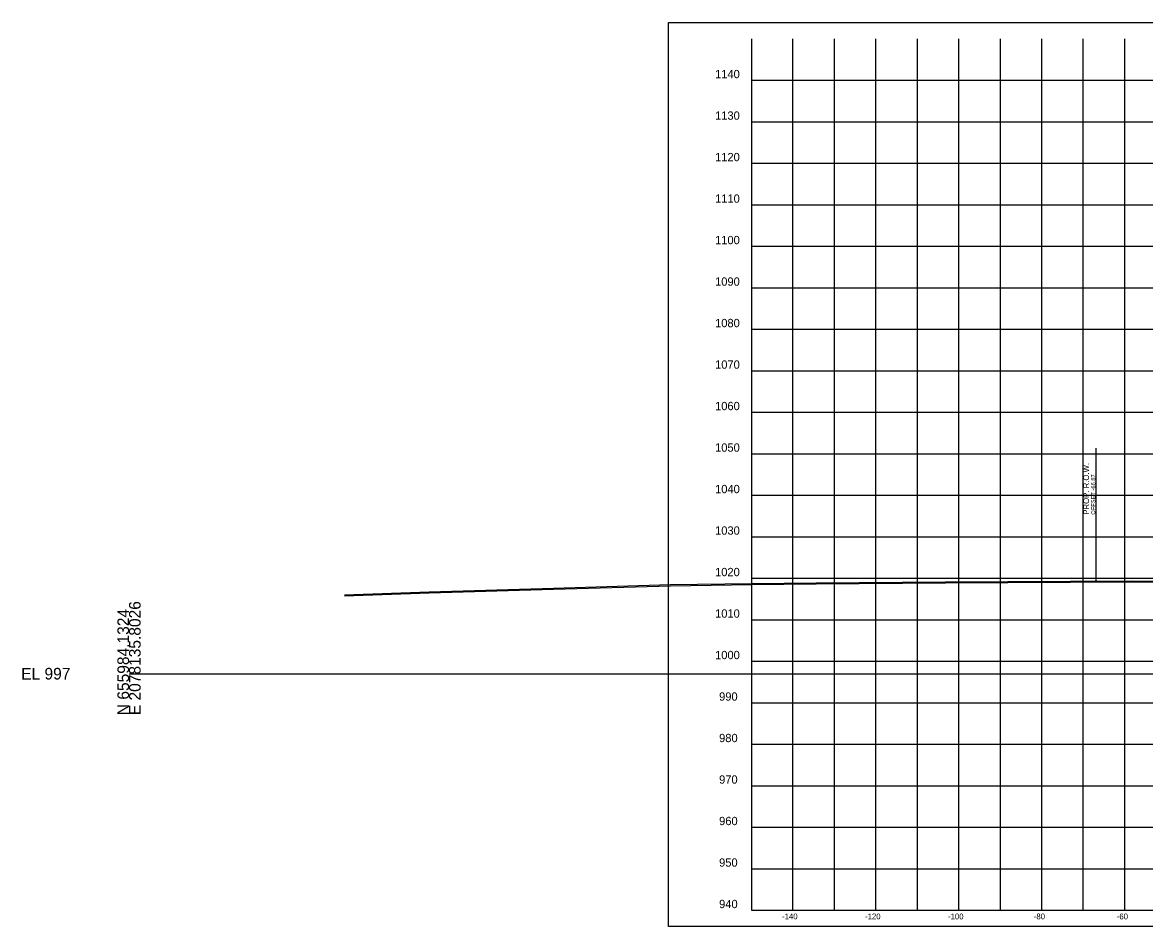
# Model space of a CAD drawing. Extents: x 5868 to 6683, y 2883 to 19120.
# Drawn here: x 5868.1 to 6138.5, y 10384.1 to 10602 of the extents above; entities that cross this region are included whole.
import ezdxf

# ---------------------------------------------------------------- set-up
doc = ezdxf.new("R2010")
doc.units = 0
for name, color, linetype in [('DESIGN - ROW - Right-of-Way and Easement Labels', 7, 'Continuous'), ('DESIGN - ROW - Right-of-Way Linework', 7, 'Continuous'), ('DESIGN - SHEET - Corner Text', 7, 'Continuous'), ('DESIGN - SHEET - Light Grid', 7, 'Continuous'), ('DESIGN - SHEET - Linework', 7, 'Continuous'), ('DESIGN - SHEET - Plot Shape', 7, 'Continuous'), ('SURVEY - GROUND - Bottom of Topsoil Layer', 7, 'Continuous'), ('SURVEY - GROUND - Top of Ground', 7, 'Continuous')]:
    doc.layers.add(name, color=color, linetype=linetype)

msp = doc.modelspace()

# ---------------------------------------------------------------- linework, layer by layer
at = {"layer": 'DESIGN - ROW - Right-of-Way Linework'}
msp.add_line((6126.91, 10467.38), (6126.91, 10499.38), dxfattribs=at)
at = {"layer": 'DESIGN - SHEET - Light Grid'}
msp.add_line((5893.78, 10445.07), (6193.78, 10445.07), dxfattribs=at)
at = {"layer": 'DESIGN - SHEET - Linework'}
for p, q in [((6053.78, 10388.07), (6053.78, 10598.07)), ((6063.78, 10388.07), (6063.78, 10598.07)), ((6073.78, 10388.07), (6073.78, 10598.07)), ((6083.78, 10388.07), (6083.78, 10598.07)), ((6093.78, 10388.07), (6093.78, 10598.07)), ((6103.78, 10388.07), (6103.78, 10598.07)), ((6113.78, 10388.07), (6113.78, 10598.07)), ((6123.78, 10388.07), (6123.78, 10598.07)), ((6133.78, 10388.07), (6133.78, 10598.07)), ((6043.78, 10588.07), (6343.78, 10588.07)), ((6043.78, 10578.07), (6343.78, 10578.07)), ((6043.78, 10568.07), (6343.78, 10568.07)), ((6043.78, 10558.07), (6343.78, 10558.07)), ((6043.78, 10548.07), (6343.78, 10548.07)), ((6043.78, 10538.07), (6343.78, 10538.07)), ((6043.78, 10528.07), (6343.78, 10528.07)), ((6043.78, 10518.07), (6343.78, 10518.07)), ((6043.78, 10508.07), (6343.78, 10508.07)), ((6043.78, 10498.07), (6343.78, 10498.07)), ((6043.78, 10488.07), (6343.78, 10488.07)), ((6043.78, 10478.07), (6343.78, 10478.07)), ((6043.78, 10468.07), (6343.78, 10468.07)), ((6043.78, 10458.07), (6343.78, 10458.07)), ((6043.78, 10448.07), (6343.78, 10448.07)), ((6043.78, 10438.07), (6343.78, 10438.07)), ((6043.78, 10428.07), (6343.78, 10428.07)), ((6043.78, 10418.07), (6343.78, 10418.07)), ((6043.78, 10408.07), (6343.78, 10408.07)), ((6043.78, 10398.07), (6343.78, 10398.07))]:
    msp.add_line(p, q, dxfattribs=at)
msp.add_lwpolyline([(6043.78, 10598.07), (6043.78, 10388.07), (6343.78, 10388.07), (6343.78, 10598.07)], dxfattribs=at)
at = {"layer": 'DESIGN - SHEET - Plot Shape'}
msp.add_lwpolyline([(6023.78, 10602.01), (6363.78, 10602.01), (6363.78, 10384.13), (6023.78, 10384.13)], close=True, dxfattribs=at)
at = {"layer": 'SURVEY - GROUND - Bottom of Topsoil Layer'}
for p, q in [((5996.12, 10465.43), (6024.26, 10466.28)), ((6024.26, 10466.28), (6043.86, 10466.56)), ((6043.86, 10466.56), (6059.39, 10466.7)), ((6059.39, 10466.7), (6090.59, 10466.98)), ((6090.59, 10466.98), (6135.73, 10467.17)), ((6135.73, 10467.17), (6145.82, 10467.09)), ((5945.72, 10463.81), (5966.12, 10464.53)), ((5966.12, 10464.53), (5996.12, 10465.43))]:
    msp.add_line(p, q, dxfattribs=at)
at = {"layer": 'SURVEY - GROUND - Top of Ground'}
msp.add_lwpolyline([(5945.72, 10464.06), (5966.12, 10464.78), (5996.12, 10465.68), (6024.26, 10466.53), (6043.86, 10466.81), (6059.39, 10466.95), (6090.59, 10467.23), (6135.73, 10467.42), (6145.82, 10467.34)], dxfattribs=at)

# ---------------------------------------------------------------- texts
at = {"layer": 'DESIGN - ROW - Right-of-Way and Easement Labels'}
for s, height, p in [('PROP. R.O.W.', 1.4, (6125.16, 10483.38)), ('OFFSET -66.87', 1, (6126.66, 10483.38))]:
    msp.add_text(s, height=height, rotation=90, dxfattribs=at).set_placement(p)
at = {"layer": 'DESIGN - SHEET - Corner Text'}
for s, height, p in [('1140', 2, (6035.03, 10588.57)), ('1130', 2, (6035.03, 10578.57)), ('1120', 2, (6035.03, 10568.57)), ('1110', 2, (6035.03, 10558.57)), ('1100', 2, (6035.03, 10548.57)), ('1090', 2, (6035.03, 10538.57)), ('1080', 2, (6035.03, 10528.57)), ('1070', 2, (6035.03, 10518.57)), ('1060', 2, (6035.03, 10508.57)), ('1050', 2, (6035.03, 10498.57)), ('1040', 2, (6035.03, 10488.57)), ('1030', 2, (6035.03, 10478.57)), ('1020', 2, (6035.03, 10468.57)), ('1010', 2, (6035.03, 10458.57)), ('1000', 2, (6035.03, 10448.57)), ('990', 2, (6036, 10438.57)), ('980', 2, (6036, 10428.57)), ('970', 2, (6036, 10418.57)), ('960', 2, (6036, 10408.57)), ('950', 2, (6036, 10398.57)), ('940', 2, (6036, 10388.57)), ('-140', 1.4, (6051.16, 10385.87)), ('-120', 1.4, (6071.16, 10385.87)), ('-100', 1.4, (6091.16, 10385.87)), ('-80', 1.4, (6111.84, 10385.87)), ('-60', 1.4, (6131.84, 10385.87))]:
    msp.add_text(s, height=height, dxfattribs=at).set_placement(p)
at = {"layer": 'DESIGN - SHEET - Light Grid'}
for s, p in [('E 2078135.8026', (5896.58, 10435.07)), ('N 655984.1324', (5893.78, 10435.07))]:
    msp.add_text(s, height=2.8, rotation=90, dxfattribs=at).set_placement(p)
msp.add_text('EL 997', height=2.8, dxfattribs=at).set_placement((5867.78, 10443.67))

doc.saveas('drawing.dxf')
